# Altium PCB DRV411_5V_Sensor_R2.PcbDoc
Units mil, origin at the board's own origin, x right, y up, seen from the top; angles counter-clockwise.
Board outline 3698.45 x 2309 mil, 2 copper layers (TopLayer, BottomLayer); 19 components, 19 nets, 65 pads, 13 vias.
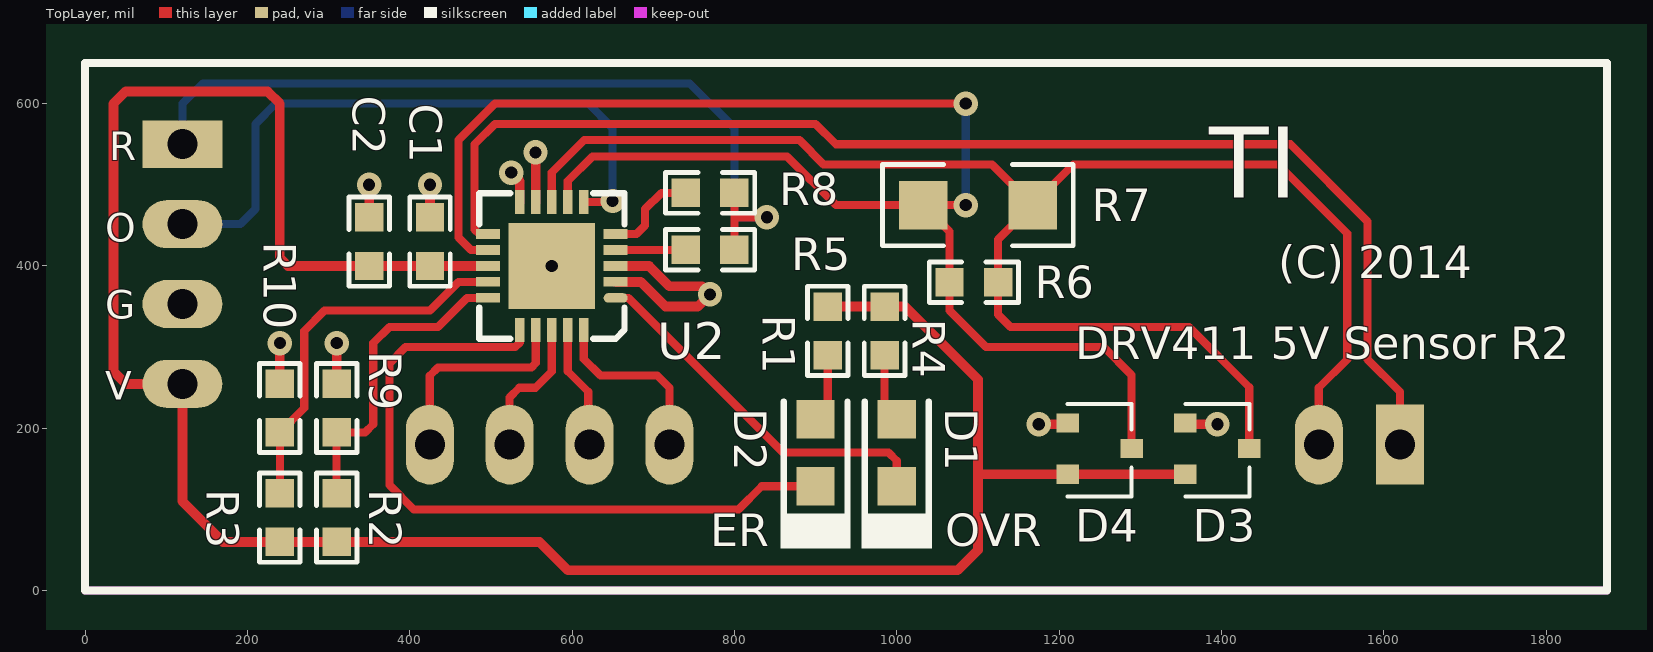
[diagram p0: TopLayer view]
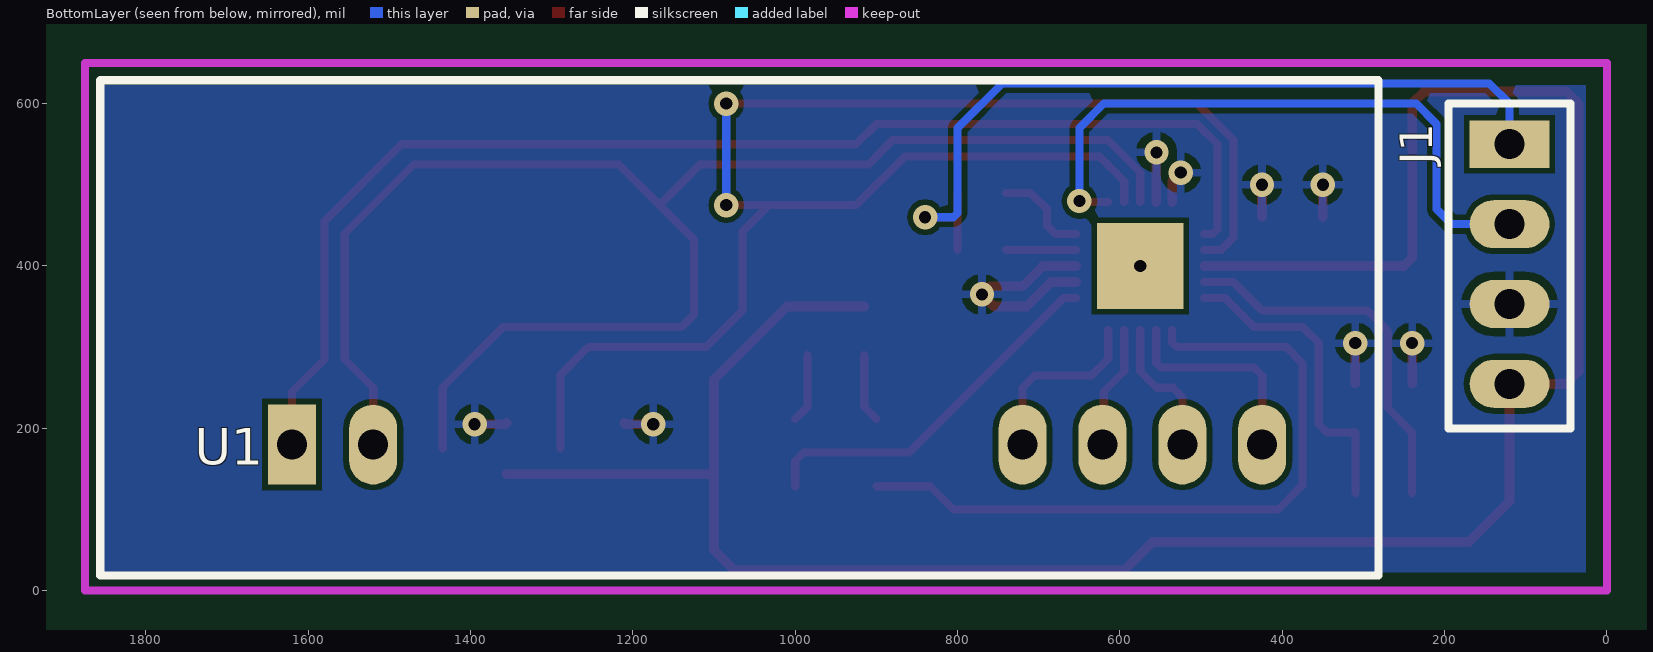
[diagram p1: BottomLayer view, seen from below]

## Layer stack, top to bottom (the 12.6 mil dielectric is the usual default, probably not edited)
TopLayer: signal copper 1.4
Dielectric: dielectric 12.6, FR-4, Dk 4.8
BottomLayer: signal copper 1.4

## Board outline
-229.5,-79.5 3468.95,-79.5 3468.95,2229.5 -229.5,2229.5

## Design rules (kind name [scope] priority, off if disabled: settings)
Clearance [All] p1: gap=7
FabricationTestPointUsage TestPointUsage [All] p1: valid=0 allowmultiple=FALSE
FabricationTestpoint Testpoint [All] p1: side=3 testpointundercomponent=TRUE minsize=40 maxsize=100 preferedsize=60 minholesize=20 maxholesize=40 preferedholesize=32 testpointgrid=1 allowsidetop=TRUE allowsidebottom=TRUE usegrid=TRUE gridtolerance=0.01
PolygonConnect [All] p1: connectstyle=Relief reliefconductorwidth=10 reliefentries=4 polygonreliefangle="90 Angle" airgapwidth=10
RoutingVias [All] p1: holewidth=20 width=50 viastyle="Through Hole" minholewidth=15 minwidth=30 maxholewidth=28 maxwidth=50
SilkscreenOverComponentPads [All] p1: minsilkscreentomaskgap=10
SolderMaskExpansion [All] p1: expansion=4
Width [All] p1: maxlimit=30 minlimit=5 preferedwidth=25
25 further rules are at their usual default settings.

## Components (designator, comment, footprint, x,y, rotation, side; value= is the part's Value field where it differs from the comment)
C1 "1uF" 0603 425,430 r90 top
C2 "10nF" 0603 350,430 r90 top
D1 "LTST-C170KSKT" LED_LTST-C170 1000,170 r270 top
D2 "LTST-C170KSKT" LED_LTST-C170 900,170 r270 top
D3 "BAT54S" SOT23 1395,175 r0 top
D4 "BAT54S" SOT23 1250,175 r0 top
J1 "HEADER-4" HDR1X4 120,550 r270 bottom
R1 "200" 0603 915,320 r270 top
R2 "NI" 0603 310,90 r90 top
R3 "NI" 0603 240,90 r90 top
R4 "200" 0603 985,320 r270 top
R5 "43" 0603 770,420 r0 top
R6 "1K" 0603 1095,380 r180 top
R7 "10" 1206 1100,475 r180 top
R8 "0" 0603 770,490 r0 top
R9 "10K" 0603 310,225 r270 top
R10 "10K" 0603 240,225 r270 top
U1 "*" TQPL_Passive 1620,180 r180 bottom locked
U2 "DRV411" "QFN-20 (RTJ)" 575,400 r180 top

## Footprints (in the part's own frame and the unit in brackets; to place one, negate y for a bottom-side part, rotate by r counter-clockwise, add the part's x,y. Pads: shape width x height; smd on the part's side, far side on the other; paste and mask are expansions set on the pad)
0603 [mil]
  rect 35x35 smd: 1(-30,0) 2(30,0)
  silkscreen extent -55,-25 55,25
1206 [mil]
  rect 60x60 smd: 1(-67.5,0) 2(67.5,0)
  silkscreen extent -118,-50 118,50
HDR1X4 [mm]
  rect 1.5x2.5 hole 0.94: 1(0,0)
  oval 1.5x2.5 hole 0.94: 2(2.5,0) 3(5,0) 4(7.5,0)
  silkscreen extent -1.27,-1.91 8.89,1.91
LED_LTST-C170 [mm] "LITE-ON"
  rect 1.2x1.2 smd: 1(-1.05,0) 2(1.05,0)
  silkscreen extent -1.6,-1.1 3,1.1, body extent -1.05,-0.67 1.05,0.67, height 1.1
"QFN-20 (RTJ)" [mm]
  oval 0.75x0.3 smd: 1(-2,1)
  rect 0.75x0.3 smd: 2(-2,0.5) 3(-2,0) 4(-2,-0.5) 5(-2,-1) 11(2,-1) 12(2,-0.5) 13(2,0) 14(2,0.5) 15(2,1)
  rect 0.3x0.75 smd: 6(-1,-2) 7(-0.5,-2) 8(0,-2) 9(0.5,-2) 10(1,-2) 16(1,2) 17(0.5,2) 18(0,2) 19(-0.5,2) 20(-1,2)
  rect 2.7x2.7 hole 0.381: 21(0,0)
  silkscreen extent -2.28,-2.28 2.28,2.28
SOT23 [mm]
  rect 0.7x0.6 smd: 1(-1,0.8) 2(-1,-0.8) 3(1,0)
  silkscreen extent -1,-1.5 1,1.4
TQPL_Passive [mm]
  rect 1.5x2.5 hole 0.94: 1(0,0)
  oval 1.5x2.5 hole 0.94: 2(2.54,0) 3(22.86,0) 4(25.36,0) 5(27.86,0) 6(30.36,0)
  silkscreen extent -6,-4.1 34,11.4

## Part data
C1 C2: library part CAP_603, "Multilayer Ceramic - 0603Size"
D1 D2: "LED, Yellow , SMD"
D3 D4: library part DUALDIODE, "Dual Schotkey"
J1: "4x1 100 mil male header"
R1 R2 R3 R4 R5 R6 R8 R9 R10: library part RES_603, "Resister - 0603Size"
R7: library part RES_1206, "Resister - 1206Size"
U1: library part TQPL_PASSIVE, "TopStek Passive Hall Sensor"

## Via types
v1: diameter 30, hole 15, TopLayer to BottomLayer, 13 vias

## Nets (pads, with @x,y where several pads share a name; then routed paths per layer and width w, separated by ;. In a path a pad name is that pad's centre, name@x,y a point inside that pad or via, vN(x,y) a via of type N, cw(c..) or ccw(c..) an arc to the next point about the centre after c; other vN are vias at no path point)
5V: C1.1 C2.1 D3.2 D4.2 J1.4 R1.1 R2.1 R3.1 R4.1 U2.13 | length 2948
  TopLayer w12: U2.13 C1.1 C2.1 250,400 240,410 240,600 225,615 50,615 35,600 35,270 50.28,254.72 J1.4 120,110 170,60 R3.1 R2.1 560,60 595,25 1075,25 1100,50 1100,145 ; R1.1 R4.1 1010,350 1100,260 1100,145 ; D3.2 D4.2 1101.5,143.5 1100,145
GND: C1.2 C2.2 D3.1 D4.1 J1.3 R9.1 R10.1 U2.2 U2.3 U2.9 U2.10 | length 624.1
  TopLayer w12: R10.1 v1(240,305) ; R9.1 v1(310,305) ; C2.2 v1(350,500) ; C1.2 v1(425,500) ; v1(525,515) 535.63,504.37 U2.10 ; v1(555,540) 555.32,539.68 U2.9 ; U2.2 684.68,380.32 715,350 755,350 v1(770,365) 760,375 720,375 695,400 U2.3 ; v1(1175,205) 1209.13,205 D4.1 ; D3.1 1357.13,205 v1(1395,205)
NetD1_1: D1.1 R4.2 | length 84.9
  TopLayer w10: R4.2 985,226.34 D1.1
NetD1_2: D1.2 U2.1 | length 460.7
  TopLayer w10: U2.1 669.37,360.63 860,170 990,170 1000,160 D1.2
NetD2_1: D2.1 R1.2 | length 84.9
  TopLayer w10: D2.1 915,226.34 R1.2
NetD2_2: D2.2 U2.16 | length 886.2
  TopLayer w10: U2.16 535.63,305.63 530,300 395,300 375,280 375,130 405,100 805,100 833.66,128.66 D2.2
NetD3_3: D3.3 R6.1 R7.1 U1.2 U2.8 | length 1971
  TopLayer w10: U2.8 575,515 615,555 880,555 910,525 1117.5,525 R7.1 ; D3.3 1434.37,250.63 1360,325 1140,325 1125,340 R6.1 1125,432.5 R7.1 ; U1.2 1520,250 1555,285 1555,440 1470,525 1217.5,525 R7.1
NetD4_3: D4.3 R6.2 R7.2 U2.7 U2.12 | length 1976.3
  TopLayer w10: U2.12 475.32,419.68 460,435 460,555 505,600 v1(1085,600) ; U2.7 594.68,504.68 625,535 865,535 925,475 R7.2 ; v1(1085,475) R7.2 ; D4.3 1289.37,265.63 1255,300 1110,300 1065,345 R6.2 1065,442.5 R7.2
  BottomLayer w10: v1(1085,475) v1(1085,600)
NetJ1_1: J1.1 R5.2 R8.2 | length 1020.2
  TopLayer w10: R5.2 800,460 ; R8.2 800,460 ; v1(840,460) 800,460
  BottomLayer w10: J1.1 120,600 145,625 745,625 800,570 800,465 805,460 v1(840,460)
NetJ1_2: J1.2 U2.6 | length 791.6
  TopLayer w10: U2.6 648.74,478.74 v1(650,480)
  BottomLayer w10: J1.2 191.57,451.57 210,470 210,575 235,600 620,600 650,570 v1(650,480)
NetR2_2: R2.2 R9.2 U2.15 | length 388.4
  TopLayer w10: R2.2 R9.2 345,195 355,205 355,305 375,325 435,325 470.63,360.63 U2.15
NetR3_2: R3.2 R10.2 U2.14 | length 463.7
  TopLayer w10: R3.2 R10.2 270,225 270,320 295,345 425,345 460.32,380.32 U2.14
NetR5_1: R5.1 U2.4 | length 86.4
  TopLayer w10: U2.4 739.68,419.68 R5.1
NetR8_1: R8.1 U2.5 | length 118.9
  TopLayer w10: U2.5 679.37,439.37 690,450 690,470 710,490 R8.1
NetU1_1: U1.1 U2.11 | length 1575.2
  TopLayer w10: U2.11 485.63,439.37 480,445 480,550 505,575 900,575 925,550 1485,550 1580,455 1580,285 1620,245 U1.1
NetU1_3: U1.3 U2.20 | length 226
  TopLayer w10: U2.20 614.37,285.63 635,265 705,265 720,250 U1.3
NetU1_4: U1.4 U2.19 | length 152.4
  TopLayer w10: U2.19 594.68,270.32 620,245 620,181.57 U1.4
NetU1_5: U1.5 U2.18 | length 174.5
  TopLayer w10: U1.5 523.15,238.15 535,250 555,250 575,270 U2.18
NetU1_6: U1.6 U2.17 | length 262.7
  TopLayer w10: U1.6 424.72,264.72 435,275 550,275 555.32,280.32 U2.17
pads on no net: U2.21

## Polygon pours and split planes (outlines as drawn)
GND on BottomLayer "BottomLayer-No Net" (solid, remove dead copper, pour order 2): 26.31,622.6 26.31,22.6 1851.31,22.6 1851.31,622.6 26.31,622.6

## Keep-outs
KeepOutLayer:
  lines w10: 0,0 1875,0 1875,650 0,650 0,0

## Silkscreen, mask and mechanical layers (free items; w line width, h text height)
TopOverlay:
  lines w10: 0,0 0,650 1875,650 1875,0 0,0
  text "R" at 30,530 h35
  text "TI" at 1385,455 h150
  text "O" at 25,430 h35
  text "(C) 2014" at 1470,385 h40
  text "G" at 25,335 h35
  text "DRV411 5V Sensor R2" at 1220,285 h40
  text "V" at 25,235 h35
  text "ER" at 770,55 h40
  text "OVR" at 1060,55 h40
DrillDrawing:
  lines w10: -200,650 -25,650 ; -195,0 -20,0 ; -120,60 -100,0 ; -120,590 -100,650 ; -110,0 -90,0 ; -110,650 -90,650 ; -100,74.08 -100,0 ; -100,575.92 -100,650 ; -80,60 -100,0 ; -80,590 -100,650 ; 0,-195 0,-20 ; 0,-140 0,-120 ; 60,-150 0,-130 ; 60,-110 0,-130 ; 661.58,-130 0,-130 ; 1213.42,-130 1875,-130 ; 1815,-150 1875,-130 ; 1815,-110 1875,-130 ; 1875,-200 1875,-25 ; 1875,-140 1875,-120
  text "650 (mil)" at -64.01,84.08 h60 r90
  text "1875 (mil)" at 671.58,-165.99 h60
  text ".Legend" at 2105,-400 h60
